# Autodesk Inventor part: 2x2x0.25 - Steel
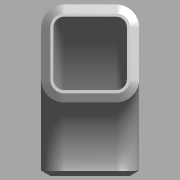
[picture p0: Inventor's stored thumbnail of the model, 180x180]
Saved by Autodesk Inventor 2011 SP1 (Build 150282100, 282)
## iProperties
Created: 2011-03
Part Number: 2x2x0.25 - Steel
Material: Default
Document SubType Name: Modeling
Designer: bamfomg
Density: 1 g/cm^3
Author: bamfomg
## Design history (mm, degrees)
derived "Square Tube Corners.ipt" dims "d2" = 25.4, "d3" = 25.4, "d6" = 6.35, "d7" = 6.35, "d8" = 6.35, "d12" = 90 deg, "d16" = 4.7625, "d18" = 30 deg, "ID_Rad" = 5.55625, "OD_Rad" = 11.90625, "Side_One" = 50.8, "Side_Two" = 50.8, "Thickness" = 6.35, "Bend_IDRad" = 38.1, "Bevel_Angl" = 30 deg, "Bevel_Dist" = 4.7625
body "Solid1"
feature "Solid1::Square Tube Corners.ipt" dims "d2" = 25.4, "d3" = 25.4, "d6" = 6.35, "d7" = 6.35, "d8" = 6.35, "d12" = 90 deg, "d16" = 4.7625, "d18" = 30 deg, "ID_Rad" = 5.55625, "OD_Rad" = 11.90625, "Side_One" = 50.8, "Side_Two" = 50.8, "Thickness" = 6.35, "Bend_IDRad" = 38.1, "Bevel_Angl" = 30 deg, "Bevel_Dist" = 4.7625, "ScaleForDerivedMember" = 10
tag "TaggingFeature1"
